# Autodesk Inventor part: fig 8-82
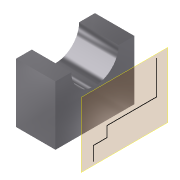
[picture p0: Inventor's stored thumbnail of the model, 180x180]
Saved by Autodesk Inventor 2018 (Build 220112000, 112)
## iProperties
Shininess: 77.0
Length Units: 11269
Angle Units: 11279
Time Units: 11290
Mass Units: 11283
Length Display Precision: 3
Angle Display Precision: 2
Created: 2002-01
Part Number: fig 8-82
Document SubType Name: Modeling
Designer: ***
Density: 1 g/cm^3
Material: Generic
Appearance: Metal-AL-6061 (Polished)
Density: 0.0
Volumn: 0.0
Area: 0.0
PropertySet Name: Model Information
Control State: 0
Master: False
Checked Out: False
Author: ***
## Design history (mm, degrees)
sketch "Sketch5"
  geometry: L1 (-22.226, 10.275)-(-14.226, 10.275); L2 (9.774, 10.275)-(17.774, 10.275); L3 (17.774, 10.275)-(17.774, -19.725); L4 (17.774, -19.725)-(-22.226, -19.725); L5 (-22.226, -19.725)-(-22.226, 10.275); A1 r 12 centre (-2.226, 10.275) between (-14.226, 10.275) and (9.774, 10.275)
  constraints: 10 end point, 2 equal length, 2 parallel, 2 point on circle, 1 centre point, 1 collinear, 1 horizontal, 1 perpendicular, 1 point on line
  dimensions: "d7" = 40 distance of L3.end L4.end; "d8" = 30 distance of L2.end L3.end; "d9" = 12 radius of A1
extrude "Extrusion2" new body sketch "Sketch5" distance "d10" = 20; taper "d11" = 0 deg
workplane "Work Plane3"
sketch "Sketch6"
  geometry: L1 (19.321, -18.091)-(12.314, -18.091); L2 (12.314, -18.091)-(12.314, -11.217); L3 (12.314, -11.217)-(7.026, -11.217); L4 (7.026, -11.217)-(7.026, 7.425); L5 (7.026, 7.425)-(7.026, 14.035); L6 (7.026, 14.035)-(-10.029, 14.035)
  constraints: 12 end point, 4 parallel, 1 horizontal, 1 perpendicular
body "Solid1"
other parameters: "d12" = 15
